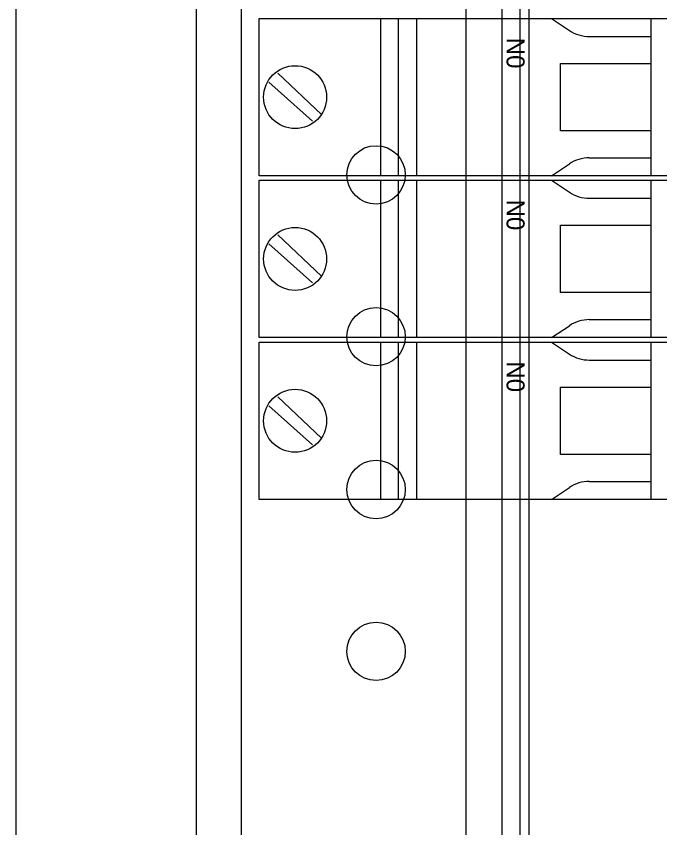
# Model space of a CAD drawing. Extents: x 0 to 4205, y 0 to 2970.
# Drawn here: x 887 to 958.5, y 1047.1 to 1137.3 of the extents above; entities that cross this region are included whole.
import ezdxf

# ---------------------------------------------------------------- set-up
doc = ezdxf.new("R2010")
doc.units = 0
doc.layers.add('02___PRT_ALL_AXES', color=7, linetype='Continuous')
doc.layers.add('Level 1', color=7, linetype='Continuous')

# ---------------------------------------------------------------- blocks, each defined once
blk = doc.blocks.new('NCX-2418-3U')
for p, q in [((-235, 137.85), (-235, -94.15)), ((-204, 132.85), (-204, -99.15)), ((-203, 132.85), (-203, -99.15)), ((-210, 124.85), (-210, -91.15)), ((-206, 124.85), (-206, -91.15))]:
    blk.add_line(p, q)
blk.add_lwpolyline([(-162.742, 163.65), (-162.742, 142.85), (-230, 142.85), (-235, 137.85), (-235, -94.15)])
for centre in [(-220, 53), (-220, 18)]:
    blk.add_circle(centre, 3.25)
at = {"layer": '02___PRT_ALL_AXES'}
for centre in [(-220, 35), (-220, 0)]:
    blk.add_circle(centre, 3.25, dxfattribs=at)

msp = doc.modelspace()

# ---------------------------------------------------------------- linework, layer by layer
at = {"layer": 'Level 1'}
for p, q in [((914.008, 1119.593), (914.008, 1137.093)), ((914.008, 1137.093), (997.008, 1137.093)), ((927.508, 1137.093), (927.508, 1119.593)), ((929.508, 1119.593), (929.508, 1137.093)), ((931.508, 1137.093), (931.508, 1119.593)), ((946.508, 1137.093), (948.5, 1135.765)), ((957.592, 1119.65), (957.592, 1137.069)), ((950.719, 1135.093), (957.592, 1135.093)), ((947.508, 1124.593), (947.508, 1132.093)), ((947.508, 1132.093), (957.592, 1132.093)), ((916.084, 1131.017), (920.931, 1126.419)), ((919.931, 1125.669), (915.084, 1130.017)), ((957.592, 1124.593), (947.508, 1124.593)), ((950.719, 1121.593), (957.592, 1121.593)), ((946.508, 1119.593), (948.5, 1120.921)), ((997.008, 1119.593), (914.008, 1119.593)), ((914.008, 1101.593), (914.008, 1119.093)), ((914.008, 1119.093), (997.008, 1119.093)), ((927.508, 1119.093), (927.508, 1101.593)), ((929.508, 1101.593), (929.508, 1119.093)), ((931.508, 1119.093), (931.508, 1101.593)), ((946.508, 1119.093), (948.5, 1117.765)), ((957.592, 1101.65), (957.592, 1119.069)), ((950.719, 1117.093), (957.592, 1117.093)), ((947.508, 1106.593), (947.508, 1114.093)), ((947.508, 1114.093), (957.592, 1114.093)), ((916.084, 1113.017), (920.931, 1108.419)), ((919.931, 1107.669), (915.084, 1112.017)), ((957.592, 1106.593), (947.508, 1106.593)), ((950.719, 1103.593), (957.592, 1103.593)), ((946.508, 1101.593), (948.5, 1102.921)), ((997.008, 1101.593), (914.008, 1101.593)), ((914.008, 1083.593), (914.008, 1101.093)), ((914.008, 1101.093), (997.008, 1101.093)), ((927.508, 1101.093), (927.508, 1083.593)), ((929.508, 1083.593), (929.508, 1101.093)), ((931.508, 1101.093), (931.508, 1083.593)), ((946.508, 1101.093), (948.5, 1099.765)), ((957.592, 1083.65), (957.592, 1101.069)), ((950.719, 1099.093), (957.592, 1099.093)), ((947.508, 1088.593), (947.508, 1096.093)), ((947.508, 1096.093), (957.592, 1096.093)), ((916.084, 1095.017), (920.931, 1090.419)), ((919.931, 1089.669), (915.084, 1094.017)), ((957.592, 1088.593), (947.508, 1088.593)), ((950.719, 1085.593), (957.592, 1085.593)), ((946.508, 1083.593), (948.5, 1084.921)), ((997.008, 1083.593), (914.008, 1083.593))]:
    msp.add_line(p, q, dxfattribs=at)
for points in [[(907.008, 963.143), (887.008, 963.143), (887.008, 1213.143), (907.008, 1213.143)], [(914.008, 1119.593), (914.008, 1137.093), (997.008, 1137.093), (997.008, 1119.593)], [(914.008, 1119.593), (914.008, 1137.093), (997.008, 1137.093), (997.008, 1119.593)], [(914.008, 1101.593), (914.008, 1119.093), (997.008, 1119.093), (997.008, 1101.593)], [(914.008, 1101.593), (914.008, 1119.093), (997.008, 1119.093), (997.008, 1101.593)], [(914.008, 1083.593), (914.008, 1101.093), (997.008, 1101.093), (997.008, 1083.593)], [(914.008, 1083.593), (914.008, 1101.093), (997.008, 1101.093), (997.008, 1083.593)]]:
    msp.add_lwpolyline(points, close=True, dxfattribs=at)
msp.add_lwpolyline([(984.266, 1213.143), (907.008, 1213.143), (907.008, 963.143), (984.029, 963.143)], dxfattribs=at)
for centre in [(918.008, 1128.343), (918.008, 1110.343), (918.008, 1092.343)]:
    msp.add_circle(centre, 3.5, dxfattribs=at)
for centre, start, end in [((950.719, 1139.093), 236.30993, 270), ((950.719, 1117.593), 90, 123.69007), ((950.719, 1121.093), 236.30993, 270), ((950.719, 1099.593), 90, 123.69007), ((950.719, 1103.093), 236.30993, 270), ((950.719, 1081.593), 90, 123.69007)]:
    msp.add_arc(centre, 4, start, end, dxfattribs=at)

# ---------------------------------------------------------------- block references
msp.add_blockref('NCX-2418-3U', (1147.008, 1066.693))

# ---------------------------------------------------------------- texts
for p in [(943.525, 1131.532), (943.525, 1113.532), (943.525, 1095.532)]:
    msp.add_text('0N', height=2, rotation=90, dxfattribs=at).set_placement(p)

doc.saveas('drawing.dxf')
